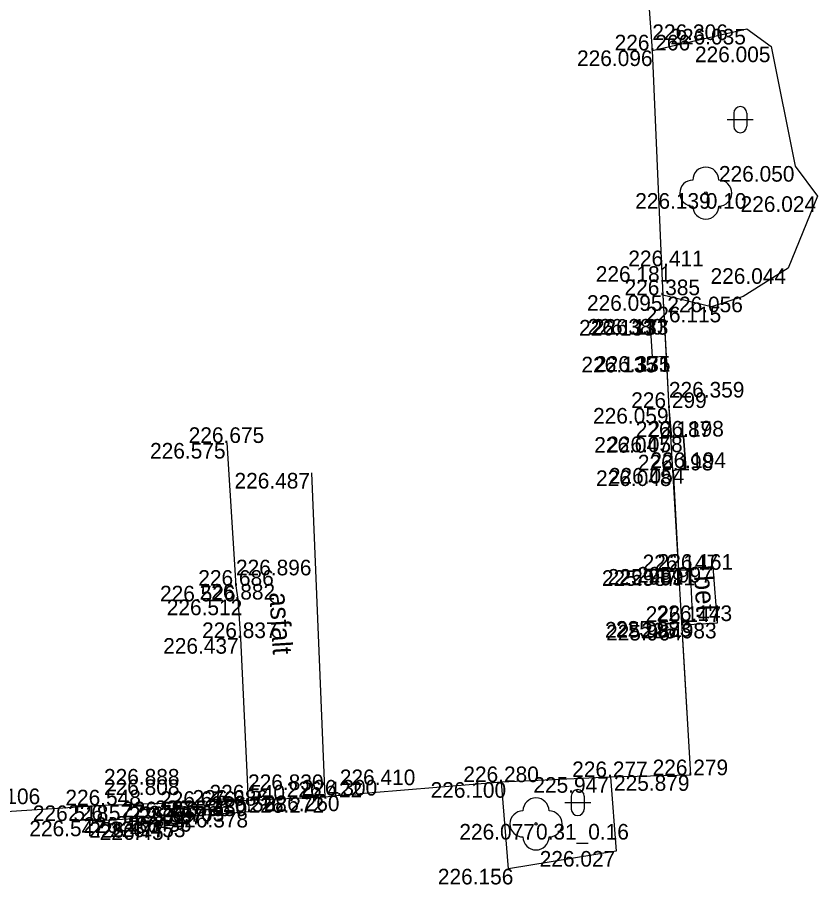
# Model space of a CAD drawing. Extents: x -599516 to -599132, y -1163668 to -1163119.
# Drawn here: x -599383.1 to -599367.73, y -1163235.96 to -1163219.3 of the extents above; entities that cross this region are included whole.
import ezdxf

# ---------------------------------------------------------------- set-up
doc = ezdxf.new("R2010")
doc.units = 0
for name, color, linetype in [('Bod-oznac1', 7, 'Continuous'), ('Bod-oznac2', 7, 'Continuous'), ('Bod-oznac3', 7, 'Continuous'), ('Bod-oznac4', 7, 'Continuous'), ('Bod-vyska1', 7, 'Continuous'), ('Bod-vyska2', 7, 'Continuous'), ('Bod-vyska3', 7, 'Continuous'), ('Bod-vyska4', 7, 'Continuous'), ('Z_cela-hrobu-dolni-linie', 7, 'Continuous'), ('Z_cela-hrobu-horni-linie', 7, 'Continuous'), ('Z_chodnik', 7, 'Continuous'), ('Z_komunikace', 7, 'Continuous'), ('Z_kultury-znacky', 7, 'Continuous'), ('Z_nove-stromy-prumer-kmene', 7, 'Continuous'), ('Z_obvod-kmene-spodek-ve-vysce1_2m', 7, 'Continuous'), ('Z_popis-budov-povrchu', 7, 'Continuous'), ('Z_povrchy-rozhrani-typu', 7, 'Continuous'), ('Z_stromy-kere', 7, 'Continuous'), ('Z_stromy-nove-vysazene', 7, 'Continuous'), ('Z_zpevnene-plochy', 7, 'Continuous')]:
    doc.layers.add(name, color=color, linetype=linetype)

msp = doc.modelspace()

# ---------------------------------------------------------------- linework, layer by layer
at = {"layer": 'Bod-oznac1'}
for p, q in [((-599369.087, -1163219.519), (-599369.087, -1163219.519)), ((-599370.902, -1163219.933), (-599370.902, -1163219.933)), ((-599368.617, -1163219.859), (-599368.617, -1163219.859)), ((-599368.156, -1163222.154), (-599368.156, -1163222.154)), ((-599369.875, -1163222.674), (-599369.875, -1163222.674)), ((-599367.726, -1163222.735), (-599367.726, -1163222.735)), ((-599370.726, -1163224.078), (-599370.726, -1163224.078)), ((-599368.292, -1163224.117), (-599368.292, -1163224.117)), ((-599370.7, -1163224.635), (-599370.7, -1163224.635)), ((-599369.156, -1163224.663), (-599369.156, -1163224.663)), ((-599369.767, -1163224.856), (-599369.767, -1163224.856)), ((-599370.942, -1163225.11), (-599370.942, -1163225.11)), ((-599370.677, -1163225.093), (-599370.677, -1163225.093)), ((-599370.675, -1163225.092), (-599370.675, -1163225.092)), ((-599370.897, -1163225.818), (-599370.897, -1163225.818)), ((-599370.637, -1163225.805), (-599370.637, -1163225.805)), ((-599370.637, -1163225.806), (-599370.637, -1163225.806)), ((-599370.583, -1163226.801), (-599370.583, -1163226.801)), ((-599379.077, -1163227.473), (-599379.077, -1163227.473)), ((-599370.536, -1163227.36), (-599370.536, -1163227.36)), ((-599370.301, -1163227.35), (-599370.301, -1163227.35)), ((-599370.256, -1163227.954), (-599370.256, -1163227.954)), ((-599377.444, -1163228.048), (-599377.444, -1163228.048)), ((-599370.503, -1163228), (-599370.503, -1163228)), ((-599370.398, -1163229.918), (-599370.398, -1163229.918)), ((-599370.392, -1163229.895), (-599370.392, -1163229.895)), ((-599370.175, -1163229.909), (-599370.175, -1163229.909)), ((-599369.732, -1163229.855), (-599369.732, -1163229.855)), ((-599378.899, -1163230.216), (-599378.899, -1163230.216)), ((-599378.862, -1163230.481), (-599378.862, -1163230.481)), ((-599370.339, -1163230.911), (-599370.339, -1163230.911)), ((-599370.319, -1163230.967), (-599370.319, -1163230.967)), ((-599370.13, -1163230.894), (-599370.13, -1163230.894)), ((-599369.647, -1163230.927), (-599369.647, -1163230.927)), ((-599378.814, -1163231.221), (-599378.814, -1163231.221)), ((-599371.704, -1163233.892), (-599371.704, -1163233.892)), ((-599370.166, -1163233.855), (-599370.166, -1163233.855)), ((-599373.798, -1163233.988), (-599373.798, -1163233.988)), ((-599377.184, -1163234.277), (-599377.184, -1163234.277)), ((-599376.904, -1163234.246), (-599376.904, -1163234.246)), ((-599381.434, -1163234.435), (-599381.434, -1163234.435)), ((-599378.667, -1163234.34), (-599378.667, -1163234.34)), ((-599379.733, -1163234.64), (-599379.733, -1163234.64)), ((-599378.644, -1163234.559), (-599378.644, -1163234.559)), ((-599381.385, -1163234.727), (-599381.385, -1163234.727)), ((-599380.358, -1163234.663), (-599380.358, -1163234.663)), ((-599380.232, -1163234.755), (-599380.232, -1163234.755)), ((-599380.033, -1163234.798), (-599380.033, -1163234.798)), ((-599379.838, -1163234.745), (-599379.838, -1163234.745)), ((-599373.136, -1163234.791), (-599373.136, -1163234.791)), ((-599371.595, -1163235.311), (-599371.595, -1163235.311)), ((-599373.666, -1163235.653), (-599373.666, -1163235.653))]:
    msp.add_line(p, q, dxfattribs=at)
at = {"layer": 'Bod-oznac2'}
for p, q in [((-599370.902, -1163219.933), (-599370.902, -1163219.933)), ((-599370.726, -1163224.078), (-599370.726, -1163224.078)), ((-599370.7, -1163224.635), (-599370.7, -1163224.635)), ((-599370.583, -1163226.801), (-599370.583, -1163226.801)), ((-599379.077, -1163227.473), (-599379.077, -1163227.473)), ((-599370.536, -1163227.36), (-599370.536, -1163227.36)), ((-599370.301, -1163227.35), (-599370.301, -1163227.35)), ((-599370.256, -1163227.954), (-599370.256, -1163227.954)), ((-599370.503, -1163228), (-599370.503, -1163228)), ((-599370.398, -1163229.918), (-599370.398, -1163229.918)), ((-599370.175, -1163229.909), (-599370.175, -1163229.909)), ((-599378.899, -1163230.216), (-599378.899, -1163230.216)), ((-599378.862, -1163230.481), (-599378.862, -1163230.481)), ((-599370.339, -1163230.911), (-599370.339, -1163230.911)), ((-599370.13, -1163230.894), (-599370.13, -1163230.894)), ((-599378.814, -1163231.221), (-599378.814, -1163231.221)), ((-599371.704, -1163233.892), (-599371.704, -1163233.892)), ((-599370.166, -1163233.855), (-599370.166, -1163233.855)), ((-599373.798, -1163233.988), (-599373.798, -1163233.988)), ((-599377.184, -1163234.277), (-599377.184, -1163234.277)), ((-599376.904, -1163234.246), (-599376.904, -1163234.246)), ((-599381.434, -1163234.435), (-599381.434, -1163234.435)), ((-599378.667, -1163234.34), (-599378.667, -1163234.34)), ((-599379.733, -1163234.64), (-599379.733, -1163234.64)), ((-599378.644, -1163234.559), (-599378.644, -1163234.559)), ((-599381.385, -1163234.727), (-599381.385, -1163234.727)), ((-599380.358, -1163234.663), (-599380.358, -1163234.663)), ((-599380.232, -1163234.755), (-599380.232, -1163234.755)), ((-599380.033, -1163234.798), (-599380.033, -1163234.798)), ((-599379.838, -1163234.745), (-599379.838, -1163234.745))]:
    msp.add_line(p, q, dxfattribs=at)
at = {"layer": 'Bod-oznac3'}
for p, q in [((-599370.902, -1163219.933), (-599370.902, -1163219.933)), ((-599370.583, -1163226.801), (-599370.583, -1163226.801)), ((-599378.899, -1163230.216), (-599378.899, -1163230.216)), ((-599376.904, -1163234.246), (-599376.904, -1163234.246)), ((-599381.434, -1163234.435), (-599381.434, -1163234.435)), ((-599378.667, -1163234.34), (-599378.667, -1163234.34)), ((-599379.733, -1163234.64), (-599379.733, -1163234.64)), ((-599380.358, -1163234.663), (-599380.358, -1163234.663))]:
    msp.add_line(p, q, dxfattribs=at)
at = {"layer": 'Bod-oznac4'}
msp.add_line((-599381.434, -1163234.435), (-599381.434, -1163234.435), dxfattribs=at)
at = {"layer": 'Z_cela-hrobu-dolni-linie'}
for p, q in [((-599370.897, -1163225.818), (-599370.637, -1163225.805)), ((-599371.704, -1163233.892), (-599373.798, -1163233.988))]:
    msp.add_line(p, q, dxfattribs=at)
for points in [[(-599370.902, -1163219.933), (-599370.726, -1163224.078), (-599370.7, -1163224.635)], [(-599370.897, -1163225.818), (-599370.942, -1163225.11), (-599370.677, -1163225.093)]]:
    msp.add_lwpolyline(points, dxfattribs=at)
at = {"layer": 'Z_cela-hrobu-horni-linie'}
for points in [[(-599370.984, -1163218.863), (-599370.902, -1163219.933), (-599370.902, -1163219.933), (-599370.726, -1163224.078), (-599370.7, -1163224.635), (-599370.675, -1163225.092), (-599370.677, -1163225.093), (-599370.637, -1163225.805), (-599370.637, -1163225.806), (-599370.583, -1163226.801), (-599370.583, -1163226.801), (-599370.166, -1163233.855)], [(-599379.077, -1163227.473), (-599378.899, -1163230.216), (-599378.899, -1163230.216), (-599378.862, -1163230.481)], [(-599370.166, -1163233.855), (-599371.704, -1163233.892), (-599373.798, -1163233.988), (-599376.904, -1163234.246), (-599376.904, -1163234.246), (-599377.184, -1163234.277), (-599377.444, -1163228.048)], [(-599378.814, -1163231.221), (-599378.667, -1163234.34), (-599381.434, -1163234.435), (-599381.434, -1163234.435), (-599384.109, -1163234.611), (-599384.109, -1163234.611), (-599384.737, -1163234.681), (-599386.749, -1163234.723), (-599387.892, -1163234.784), (-599388.267, -1163234.806), (-599389.432, -1163234.871), (-599391.976, -1163235.023), (-599391.976, -1163235.023), (-599392.445, -1163235.04), (-599392.445, -1163235.04), (-599392.853, -1163235.069), (-599392.853, -1163235.069), (-599393.336, -1163235.072), (-599393.336, -1163235.072), (-599396.048, -1163235.23), (-599396.048, -1163235.23), (-599398.782, -1163235.373), (-599398.884, -1163232.087)]]:
    msp.add_lwpolyline(points, dxfattribs=at)
at = {"layer": 'Z_chodnik'}
for points in [[(-599379.077, -1163227.473), (-599378.899, -1163230.216), (-599378.862, -1163230.481), (-599378.814, -1163231.221), (-599378.667, -1163234.34)], [(-599377.184, -1163234.277), (-599377.444, -1163228.048)]]:
    msp.add_lwpolyline(points, dxfattribs=at)
at = {"layer": 'Z_komunikace'}
for points in [[(-599370.984, -1163218.863), (-599370.902, -1163219.933), (-599369.087, -1163219.519), (-599368.617, -1163219.859), (-599368.156, -1163222.154), (-599367.726, -1163222.735), (-599368.292, -1163224.117), (-599369.156, -1163224.663), (-599369.767, -1163224.856), (-599370.7, -1163224.635), (-599370.583, -1163226.801), (-599370.536, -1163227.36), (-599370.301, -1163227.35), (-599370.256, -1163227.954), (-599370.503, -1163228), (-599370.398, -1163229.918), (-599370.175, -1163229.909), (-599370.13, -1163230.894), (-599370.339, -1163230.911), (-599370.166, -1163233.855)], [(-599370.166, -1163233.855), (-599371.704, -1163233.892), (-599371.595, -1163235.311), (-599373.666, -1163235.653), (-599373.798, -1163233.988), (-599376.904, -1163234.246), (-599377.184, -1163234.277)], [(-599377.184, -1163234.277), (-599378.667, -1163234.34), (-599378.644, -1163234.559)], [(-599378.644, -1163234.559), (-599379.733, -1163234.64), (-599379.838, -1163234.745), (-599380.033, -1163234.798), (-599380.232, -1163234.755), (-599380.358, -1163234.663), (-599381.385, -1163234.727), (-599381.434, -1163234.435), (-599384.109, -1163234.611)]]:
    msp.add_lwpolyline(points, dxfattribs=at)
at = {"layer": 'Z_kultury-znacky'}
for p, q in [((-599369.337, -1163221.137), (-599369.337, -1163221.387)), ((-599369.087, -1163221.137), (-599369.087, -1163221.387)), ((-599369.462, -1163221.262), (-599368.962, -1163221.262)), ((-599372.46, -1163234.255), (-599372.46, -1163234.505)), ((-599372.21, -1163234.255), (-599372.21, -1163234.505)), ((-599372.585, -1163234.38), (-599372.085, -1163234.38))]:
    msp.add_line(p, q, dxfattribs=at)
for centre, start, end in [((-599369.212, -1163221.138), 0, 180), ((-599369.212, -1163221.388), 180, 0), ((-599372.335, -1163234.255), 0, 180), ((-599372.335, -1163234.505), 180, 0)]:
    msp.add_arc(centre, 0.125, start, end, dxfattribs=at)
at = {"layer": 'Z_povrchy-rozhrani-typu'}
msp.add_lwpolyline([(-599370.319, -1163230.967), (-599369.647, -1163230.927), (-599369.732, -1163229.855), (-599370.392, -1163229.895)], dxfattribs=at)
at = {"layer": 'Z_stromy-kere'}
msp.add_circle((-599373.136, -1163234.791), 0.025, dxfattribs=at)
for centre, start, end in [((-599373.136, -1163234.541), 0, 180), ((-599373.386, -1163234.791), 90, 270), ((-599372.886, -1163234.791), 270, 90), ((-599373.136, -1163235.041), 180, 0)]:
    msp.add_arc(centre, 0.25, start, end, dxfattribs=at)
at = {"layer": 'Z_stromy-nove-vysazene'}
msp.add_circle((-599369.875, -1163222.674), 0.025, dxfattribs=at)
for centre, start, end in [((-599369.875, -1163222.424), 0, 180), ((-599370.125, -1163222.674), 90, 270), ((-599369.625, -1163222.674), 270, 90), ((-599369.875, -1163222.924), 180, 0)]:
    msp.add_arc(centre, 0.25, start, end, dxfattribs=at)
at = {"layer": 'Z_zpevnene-plochy'}
for points in [[(-599370.503, -1163228), (-599370.256, -1163227.954), (-599370.301, -1163227.35), (-599370.536, -1163227.36)], [(-599370.398, -1163229.918), (-599370.175, -1163229.909), (-599370.13, -1163230.894), (-599370.339, -1163230.911)], [(-599380.358, -1163234.663), (-599380.358, -1163234.663), (-599381.385, -1163234.727), (-599381.434, -1163234.435)], [(-599378.667, -1163234.34), (-599378.644, -1163234.559), (-599379.733, -1163234.64), (-599379.733, -1163234.64)], [(-599380.358, -1163234.663), (-599380.232, -1163234.755), (-599380.033, -1163234.798), (-599379.838, -1163234.745), (-599379.733, -1163234.64)]]:
    msp.add_lwpolyline(points, dxfattribs=at)

# ---------------------------------------------------------------- texts
at = {"layer": 'Bod-vyska1'}
for s, p in [('226.035', (-599370.555, -1163219.819)), ('226.096', (-599372.348, -1163220.233)), ('226.005', (-599370.083, -1163220.159)), ('226.050', (-599369.622, -1163222.454)), ('226.139', (-599371.23, -1163222.974)), ('226.024', (-599369.206, -1163223.035)), ('226.181', (-599371.988, -1163224.378)), ('226.044', (-599369.783, -1163224.417)), ('226.095', (-599372.157, -1163224.935)), ('226.056', (-599370.613, -1163224.963)), ('226.115', (-599371.029, -1163225.156)), ('226.133', (-599372.308, -1163225.41)), ('226.380', (-599372.143, -1163225.392)), ('226.133', (-599372.043, -1163225.393)), ('226.135', (-599372.263, -1163226.118)), ('226.371', (-599372.005, -1163226.106)), ('226.135', (-599372.003, -1163226.105)), ('226.059', (-599372.04, -1163227.101)), ('226.575', (-599380.549, -1163227.773)), ('226.047', (-599372.017, -1163227.66)), ('226.058', (-599371.769, -1163227.65)), ('226.054', (-599371.736, -1163228.254)), ('226.487', (-599378.927, -1163228.348)), ('226.048', (-599371.983, -1163228.3)), ('225.987', (-599371.87, -1163230.218)), ('225.981', (-599371.758, -1163230.195)), ('225.991', (-599371.53, -1163230.209)), ('225.997', (-599371.193, -1163230.155)), ('226.526', (-599380.358, -1163230.516)), ('226.512', (-599380.228, -1163230.781)), ('225.987', (-599371.811, -1163231.211)), ('225.964', (-599371.789, -1163231.267)), ('225.983', (-599371.6, -1163231.194)), ('225.983', (-599371.117, -1163231.227)), ('226.437', (-599380.297, -1163231.521)), ('225.947', (-599373.187, -1163234.192)), ('225.879', (-599371.638, -1163234.155)), ('226.100', (-599375.16, -1163234.288)), ('226.272', (-599378.656, -1163234.577)), ('226.260', (-599378.361, -1163234.546)), ('226.518', (-599382.8, -1163234.735)), ('226.350', (-599380.135, -1163234.64)), ('226.436', (-599381.203, -1163234.94)), ('226.378', (-599380.116, -1163234.859)), ('226.547', (-599382.868, -1163235.027)), ('226.486', (-599381.828, -1163234.963)), ('226.477', (-599381.717, -1163235.055)), ('226.457', (-599381.516, -1163235.098)), ('226.453', (-599381.319, -1163235.045)), ('226.077', (-599374.608, -1163235.091)), ('226.027', (-599373.065, -1163235.611)), ('226.156', (-599375.021, -1163235.953))]:
    msp.add_text(s, height=0.3, dxfattribs=at).set_placement(p)
at = {"layer": 'Bod-vyska2'}
for s, p in [('226.266', (-599371.626, -1163219.933)), ('226.411', (-599371.363, -1163224.078)), ('226.385', (-599371.435, -1163224.635)), ('226.299', (-599371.307, -1163226.801)), ('226.187', (-599371.22, -1163227.36)), ('226.198', (-599370.978, -1163227.35)), ('226.675', (-599379.807, -1163227.473)), ('226.194', (-599370.939, -1163227.954)), ('226.198', (-599371.18, -1163228)), ('226.147', (-599371.088, -1163229.918)), ('226.161', (-599370.8, -1163229.909)), ('226.686', (-599379.623, -1163230.216)), ('226.882', (-599379.597, -1163230.481)), ('226.147', (-599371.029, -1163230.911)), ('226.143', (-599370.819, -1163230.894)), ('226.837', (-599379.55, -1163231.221)), ('226.277', (-599372.441, -1163233.892)), ('226.279', (-599370.896, -1163233.855)), ('226.280', (-599374.532, -1163233.988)), ('226.422', (-599377.925, -1163234.277)), ('226.300', (-599377.637, -1163234.246)), ('226.548', (-599382.175, -1163234.435)), ('226.540', (-599379.407, -1163234.34)), ('226.568', (-599379.373, -1163234.559)), ('226.577', (-599382.122, -1163234.727)), ('226.556', (-599381.087, -1163234.663)), ('226.697', (-599380.957, -1163234.755)), ('226.703', (-599380.573, -1163234.745)), ('226.566', (-599380.457, -1163234.64)), ('226.677', (-599380.764, -1163234.798))]:
    msp.add_text(s, height=0.3, dxfattribs=at).set_placement(p)
at = {"layer": 'Bod-vyska3'}
for s, p in [('226.306', (-599370.902, -1163219.733)), ('226.359', (-599370.583, -1163226.601)), ('226.896', (-599378.899, -1163230.016)), ('226.410', (-599376.904, -1163234.046)), ('226.808', (-599381.434, -1163234.235)), ('226.830', (-599378.667, -1163234.14)), ('227.106', (-599384.109, -1163234.411)), ('226.686', (-599379.733, -1163234.44)), ('226.676', (-599380.358, -1163234.463))]:
    msp.add_text(s, height=0.3, dxfattribs=at).set_placement(p)
at = {"layer": 'Bod-vyska4'}
msp.add_text('226.888', height=0.3, dxfattribs=at).set_placement((-599381.434, -1163234.035))
at = {"layer": 'Z_nove-stromy-prumer-kmene'}
msp.add_text('0.10', height=0.3, dxfattribs=at).set_placement((-599369.875, -1163222.974))
at = {"layer": 'Z_obvod-kmene-spodek-ve-vysce1_2m'}
msp.add_text('0.31_0.16', height=0.3, dxfattribs=at).set_placement((-599373.136, -1163235.091))
at = {"layer": 'Z_popis-budov-povrchu'}
for s, rotation, p in [('bet.', 273.9446, (-599370.101, -1163230.031)), ('asfalt', 273.4503, (-599378.26, -1163230.348))]:
    msp.add_text(s, height=0.375, rotation=rotation, dxfattribs=at).set_placement(p)

doc.saveas('drawing.dxf')
